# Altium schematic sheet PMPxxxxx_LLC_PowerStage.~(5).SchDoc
size 431 x 279 mm; Date: Not shown in title block; ApprovedBy: Not shown in title block; CheckedBy: Not shown in title block; Author: Not shown in title block; CompanyName: Not shown in title block; Engineer: Not shown in title block; Organization: Not shown in title block; Address1: Not shown in title block; Address2: Not shown in title block; Address3: Not shown in title block; Address4: Not shown in title block; DocumentNumber: 2; Revision: Use project parameter SCH_Rev; SheetNumber: 2; SheetTotal: 4; PageSetup: Record=PageOptions¦CenterHorizontal=True¦CenterVertical=True¦PrintScale=1.00¦XCorrection=1.00¦YCorrection=1.00¦PrintKind=0¦BorderSize=5000000¦LeftOffset=0¦BottomOffset=0¦Orientation=2¦PaperLength=1000¦PaperWidth=1000¦Scale=100¦PaperSource=15¦PrintQuality=600¦MediaType=1¦DitherType=10¦PaperKind=Letter¦PrintScaleMode=1
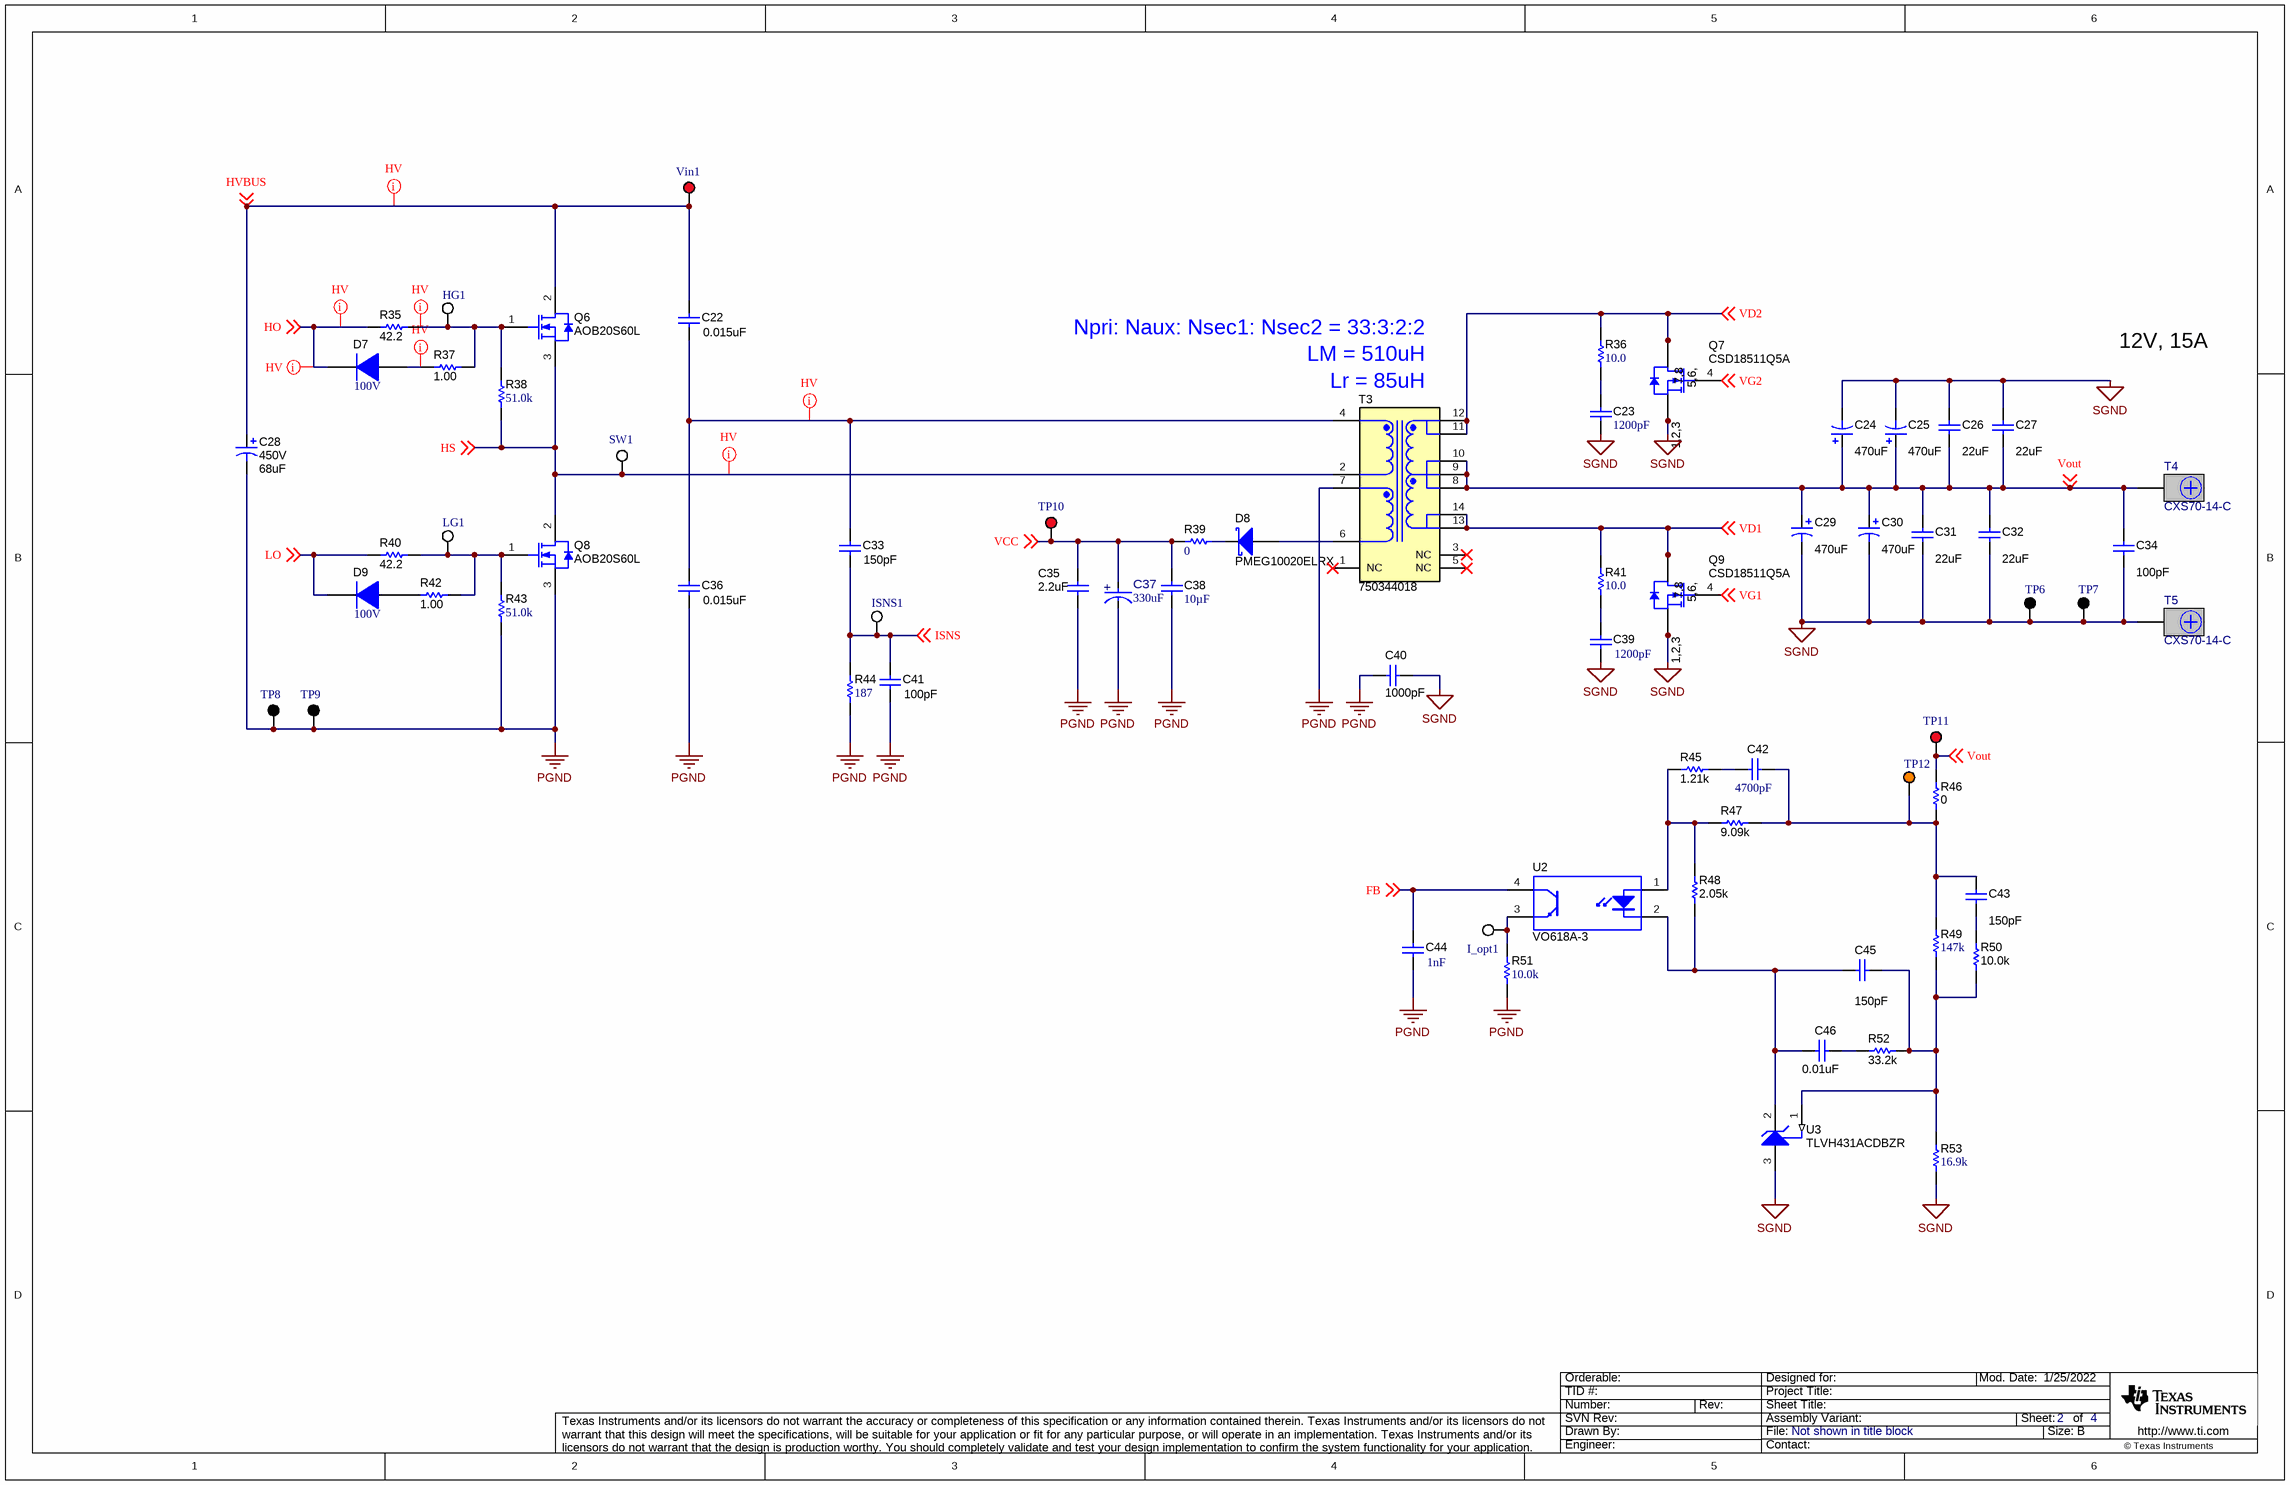
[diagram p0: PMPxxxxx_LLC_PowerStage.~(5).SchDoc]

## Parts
C22  ValueDisplayed: 0.015uF  [B32652_1800x700x1250]  (hidden comment: B32652A7153J000)
C23  ValueDisplayed: 1200pF  [0805L]  (hidden comment: GRM2165C2A122JA01D)
C24  ValueDisplayed: 470uF  [HW_1000x1600]  (hidden comment: UHW1V471MPD)
C25  ValueDisplayed: 470uF  [HW_1000x1600]  (hidden comment: UHW1V471MPD)
C26  ValueDisplayed: 22uF  [1206_190L]  (hidden comment: C3216X5R1E226M160AB)
C27  ValueDisplayed: 22uF  [1206_190L]  (hidden comment: C3216X5R1E226M160AB)
C28  VDC_V: 450V  ValueDisplayed: 68uF  [KXG_1800x3150]  (hidden comment: EKXG451ELL680MMN3S)
C29  ValueDisplayed: 470uF  [HW_1000x1600]  (hidden comment: UHW1V471MPD)
C30  ValueDisplayed: 470uF  [HW_1000x1600]  (hidden comment: UHW1V471MPD)
C31  ValueDisplayed: 22uF  [1206_190L]  (hidden comment: C3216X5R1E226M160AB)
C32  ValueDisplayed: 22uF  [1206_190L]  (hidden comment: C3216X5R1E226M160AB)
C33  ValueDisplayed: 150pF  [1206L]  (hidden comment: GRM31A5C2J151JW01D)
C34  ValueDisplayed: 100pF  [0603L]  (hidden comment: 06035A101FAT2A)
C35  ValueDisplayed: 2.2uF  [0805L]  (hidden comment: C2012X7R1V225K085AC)
C36  ValueDisplayed: 0.015uF  [B32652_1800x700x1250]  (hidden comment: B32652A7153J000)
C37  ValueDisplayed: 330uF  [FP-35ZL330MEFC10X16_RADIAL-MFG]  (hidden comment: 35ZL330MEFC10X16)
C38  ValueDisplayed: 10µF  [1206_180]  (hidden comment: C1206C106J3RACAUTO)
C39  ValueDisplayed: 1200pF  [0805L]  (hidden comment: GRM2165C2A122JA01D)
C40  ValueDisplayed: 1000pF  [CD45_700x600x1100]  (hidden comment: CD45-E2GA102M-NKA)
C41  ValueDisplayed: 100pF  [1206L]  (hidden comment: 12061A101JAT2A)
C42  ValueDisplayed: 4700pF  [0603L]  (hidden comment: C0603C472J1GAC7867)
C43  ValueDisplayed: 150pF  [0402L]  (hidden comment: 885012005062)
C44  Cap_F: 1nF  [1206L]  (hidden comment: 12061A102JAT2A)
C45  ValueDisplayed: 150pF  [0402L]  (hidden comment: 885012005062)
C46  ValueDisplayed: 0.01uF  [0603L]  (hidden comment: 06031C103JAT2A)
D7  Vr_V: 100V  [SOD-123]  (hidden comment: 1N4148W-7-F)
D8  PMEG10020ELRX  [SOD-123W]
D9  Vr_V: 100V  [SOD-123]  (hidden comment: 1N4148W-7-F)
HG1  5012  [Keystone5012]  (value not drawn)
I_opt1  5012  [Keystone5012]  (value not drawn)
ISNS1  5012  [Keystone5012]  (value not drawn)
LG1  5012  [Keystone5012]  (value not drawn)
Q6  AOB20S60L  [DDPAK]
Q7  CSD18511Q5A  [DQJ0008A]
Q8  AOB20S60L  [DDPAK]
Q9  CSD18511Q5A  [DQJ0008A]
R35  ValueDisplayed: 42.2  [0603]  (hidden comment: RC0603FR-0742R2L)
R36  ValueDisplayed: 10.0  [1206L]  (hidden comment: RC1206FR-0710RL)
R37  ValueDisplayed: 1.00  [0603L]  (hidden comment: RC0603FR-071RL)
R38  ValueDisplayed: 51.0k  [0603L]  (hidden comment: RC0603FR-0751KL)
R39  ValueDisplayed: 0  [1206L]  (hidden comment: ERJ-8GEY0R00V)
R40  ValueDisplayed: 42.2  [0603L]  (hidden comment: RC0603FR-0742R2L)
R41  ValueDisplayed: 10.0  [1206L]  (hidden comment: RC1206FR-0710RL)
R42  ValueDisplayed: 1.00  [0603L]  (hidden comment: RC0603FR-071RL)
R43  ValueDisplayed: 51.0k  [0603L]  (hidden comment: RC0603FR-0751KL)
R44  ValueDisplayed: 187  [1206]  (hidden comment: RC1206FR-07187RL)
R45  ValueDisplayed: 1.21k  [0603L]  (hidden comment: RC0603FR-071K21L)
R46  ValueDisplayed: 0  [0402L]  (hidden comment: RC0402JR-070RL)
R47  ValueDisplayed: 9.09k  [0603L]  (hidden comment: RC0603FR-079K09L)
R48  ValueDisplayed: 2.05k  [0603L]  (hidden comment: RC0603FR-072K05L)
R49  ValueDisplayed: 147k  [0603L]  (hidden comment: RC0603FR-07147KL)
R50  ValueDisplayed: 10.0k  [0603L]  (hidden comment: ERJ-3EKF1002V)
R51  ValueDisplayed: 10.0k  [0402L]  (hidden comment: ERJ-2RKF1002X)
R52  ValueDisplayed: 33.2k  [0603L]  (hidden comment: RC0603FR-0733K2L)
R53  ValueDisplayed: 16.9k  [0603L]  (hidden comment: RC0603FR-0716K9L)
SW1  5012  [Keystone5012]  (value not drawn)
T3  750344018  [Wurth_750344018]
T4  CXS70-14-C  [Panduit_CXS70-14-C]
T5  CXS70-14-C  [Panduit_CXS70-14-C]
TP6  5011  [Keystone5011]  (value not drawn)
TP7  5011  [Keystone5011]  (value not drawn)
TP8  5011  [Keystone5011]  (value not drawn)
TP9  5011  [Keystone5011]  (value not drawn)
TP10  5010  [Keystone5010]  (value not drawn)
TP11  5010  [Keystone5010]  (value not drawn)
TP12  5013  [Keystone5013]  (value not drawn)
U2  VO618A-3  [DIP-4]
U3  TLVH431ACDBZR  [DBZ0003A_N]
Vin1  5010  [Keystone5010]  (value not drawn)

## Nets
PGND: C28.2(-) C35.2 C36.2 C37.1(CATHODE) C38.2 C40.2 C41.2 C44.2 Q8.3(S) R43.1 R44.1 R51.1 T3.7 TP8.1 TP9.1
SGND: C23.2 C24.2(-) C25.2(-) C26.1 C27.1 C29.2(-) C30.2(-) C31.2 C32.2 C34.2 C39.2 C40.1 Q7.1(S) Q7.2(S) Q7.3(S) Q9.1(S) Q9.2(S) Q9.3(S) R53.1 T5.1 TP6.1 TP7.1 U3.3(ANODE)
FB: C44.1 U2.4(C) ; off-sheet FB
HO: D7.1(K) R35.1 ; off-sheet HO
HS: Q6.3(S) Q8.2(D) R38.1 SW1.1 T3.2 ; off-sheet HS
HVBUS: C22.1 C28.1(+) Q6.2(D) Vin1.1 ; off-sheet HVBUS
ISNS: C33.2 C41.1 ISNS1.1 R44.2 ; off-sheet ISNS
LO: D9.1(K) R40.1 ; off-sheet LO
VCC: C35.1 C37.2(ANODE) C38.1 R39.1 TP10.1 ; off-sheet VCC
VD1: Q9.5(D) Q9.6(D) Q9.7(D) Q9.8(D) Q9.9(D) R41.2 T3.13 T3.14 ; off-sheet VD1
VD2: Q7.5(D) Q7.6(D) Q7.7(D) Q7.8(D) Q7.9(D) R36.2 T3.11 T3.12 ; off-sheet VD2
VG1: Q9.4(G) ; off-sheet VG1
VG2: Q7.4(G) ; off-sheet VG2
Vout: C24.1(+) C25.1(+) C26.2 C27.2 C29.1(+) C30.1(+) C31.1 C32.1 C34.1 R46.2 T3.8 T3.9 T3.10 T4.1 TP11.1 ; off-sheet Vout
NetC22_2: C22.2 C33.1 C36.1 T3.4
NetC23_1: C23.1 R36.1
NetC39_1: C39.1 R41.1
NetC42_1: C42.1 C43.1 R46.1 R47.2 R49.2 TP12.1
NetC42_2: C42.2 R45.2
NetC43_2: C43.2 R50.2
NetC45_1: C45.1 R49.1 R50.1 R52.1 R53.2 U3.1(REF)
NetC45_2: C45.2 C46.2 R48.1 U2.2(K) U3.2(CATHODE)
NetC46_1: C46.1 R52.2
NetD7_2: D7.2(A) R37.1
NetD8_1: D8.1(K) R39.2
NetD8_2: D8.2(A) T3.6
NetD9_2: D9.2(A) R42.1
NetHG1_1: HG1.1 Q6.1(G) R35.2 R37.2 R38.2
NetI_opt1_1: I_opt1.1 R51.2 U2.3(E)
NetLG1_1: LG1.1 Q8.1(G) R40.2 R42.2 R43.2
NetR45_1: R45.1 R47.1 R48.2 U2.1(A)

Not connected (* = marked no-connect by the designer): T3 1(NC)* 3(NC)* 5(NC)*

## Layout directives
net class HV: HO, HS, HVBUS, NetC22_2, NetD7_2, NetHG1_1

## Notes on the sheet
- LM = 510uH
- Npri: Naux: Nsec1: Nsec2 = 33:3:2:2
- 12V, 15A
- (near T3) Lr = 85uH

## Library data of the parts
C22 C36 = CMP-0012346-3: CAP, Film, 0.015 uF, 1250 V, +/- 5%, AEC-Q200 Grade 3, TH; Manufacturer: TDK; TaMin_C: -55°C; Polarized: N; SizeAreaWB_mm2: 180; Value1: Unknown; TaMax_C: 100°C; SizeZ_mm: 12.5; SizeX_mm: 18; SizeY_mm: 7; Cap_Case: 18x7x12.5; Value2: 1250V; SizeArea_mm2: 126; CompType: Capacitor; AEC Qualified: Y; Cap_F: 15nF; VDC_V: 1.25kV; AEC Grade: 3; AEC Category: Q200
C23 C39 = CMP-0008098-2: CAP, CERM, 1200 pF, 100 V, +/- 5%, C0G/NP0, 0805; Manufacturer: MuRata; TaMin_C: -55°C; Polarized: N; SizeAreaWB_mm2: 6.75; Value1: Unknown; U/M: EA; Value: 1200pF; TaMax_C: 125°C; SizeZ_mm: 1.45; SizeX_mm: 2; SizeY_mm: 1.25; Cap_Case: 0805; Value2: 100V; SizeArea_mm2: 2.5; Cap_F: 1.2nF; AEC Category: Q200
C24 C25 C29 C30 = CMP-0010541-2: CAP, AL, 470 uF, 35 V, +/- 20%, 0.03 ohm, TH; Manufacturer: Nichicon; TaMin_C: -40°C; ESR_ohm: 0.03; Polarized: Y; SizeAreaWB_mm2: 144; U/M: EA; Value: 470uF; TaMax_C: 105°C; SizeZ_mm: 17.5; SizeX_mm: 10; Cap_Case: 10x16mm; Value2: 35V; SizeArea_mm2: 100; CompType: Capacitor; AEC Qualified: N; Cap_F: 470µF; IRMS_A: 2A; AEC Category: Q200
C26 C27 C31 C32 = CMP-0008654-2: CAP, CERM, 22 uF, 25 V, +/- 20%, X5R, 1206_190; Manufacturer: TDK; TaMin_C: -55°C; Polarized: N; SizeAreaWB_mm2: 10.92; Value1: Unknown; U/M: EA; Value: 22uF; TaMax_C: 85°C; SizeZ_mm: 1.9; SizeX_mm: 3.2; SizeY_mm: 1.6; Cap_Case: 1206; Value2: 25V; SizeArea_mm2: 5.12; CompType: Capacitor; Cap_F: 22µF; AEC Category: Q200
C28 = CMP-0010043-2: CAP, AL, 68 uF, 450 V, +/- 20%, TH; Manufacturer: Chemi-Con; TaMin_C: -25°C; Polarized: Y; SizeAreaWB_mm2: 400; Value1: Unknown; U/M: EA; Value: 68uF; TaMax_C: 105°C; SizeZ_mm: 33; SizeX_mm: 18; Cap_Case: 18x31.5mm; SizeArea_mm2: 324; CompType: Capacitor; Cap_F: 68µF; IRMS_A: 6.3dA; AEC Category: Q200
C33 = CMP-0008885-2: CAP, CERM, 150 pF, 630 V, +/- 5%, C0G/NP0, 1206; Manufacturer: MuRata; TaMin_C: -55°C; Polarized: N; SizeAreaWB_mm2: 10.92; Value1: Unknown; U/M: EA; Value: 150pF; TaMax_C: 125°C; SizeZ_mm: 1.35; SizeX_mm: 3.2; SizeY_mm: 1.6; Cap_Case: 1206; Value2: 630V; SizeArea_mm2: 5.12; CompType: Capacitor; AEC Category: Q200
C34 = CMP-0006762-4: CAP, CERM, 100 pF, 50 V, +/- 1%, C0G/NP0, 0603; Manufacturer: AVX; TaMin_C: -55°C; Polarized: N; SizeAreaWB_mm2: 4.68; Value1: Unknown; U/M: EA; TaMax_C: 125°C; SizeZ_mm: 1; SizeX_mm: 1.6; SizeY_mm: 0.8; Cap_Case: 0603; Value2: 50V; SizeArea_mm2: 1.28; CompType: Capacitor; Value: 100pF; AEC Category: Q200
C35 = CMP-0007883-2: CAP, CERM, 2.2 uF, 35 V, +/- 10%, X7R, 0805; Manufacturer: TDK; TaMin_C: -55°C; Polarized: N; SizeAreaWB_mm2: 6.75; Value1: Unknown; U/M: EA; Value: 2.2uF; TaMax_C: 125°C; SizeZ_mm: 1.45; SizeX_mm: 2; SizeY_mm: 1.25; Cap_Case: 0805; Value2: 35V; SizeArea_mm2: 2.5; CompType: Capacitor; Cap_F: 2.2µF; AEC Category: Q200
C37 = CMP-0098283-1: Cap Aluminum Lytic 330uF 35V 20% (10 X 16mm) Radial 5mm 1430mA 4000h 105C Bulk; Manufacturer: Rubycon; AEC Qualified: No; Cap_F: 330µF; IRMS_A: 1.43A; SizeZ_mm: 17.5mm; Dissipation Factor: 12%; Leakage Current: 115.5uA; Life: 4000Hours; Value: 330µF
C38 = CMP-0081062-1: CAP, CERM, 10 µF, 25 V,+/- 5%, X7R, AEC-Q200 Grade 1, 1206; Manufacturer: Kemet; TaMin_C: -55°C; Polarized: N; SizeAreaWB_mm2: 10.92; U/M: EA; Value: 10uF; TaMax_C: 125°C; SizeZ_mm: 1.8; SizeX_mm: 3.2; SizeY_mm: 1.6; Value2: 25V; SizeArea_mm2: 5.12; AEC Qualified: Y; AEC Grade: 1; AEC Category: Q200
C40 = CMP-0009595-2: CAP, CERM, 1000 pF,  V, +/- 20%, E, D7xT6mm; Manufacturer: TDK; TaMin_C: -25°C; Polarized: N; SizeAreaWB_mm2: 101.2; Value1: Unknown; U/M: EA; Value: 1000pF; TaMax_C: 125°C; SizeZ_mm: 11; SizeX_mm: 10.65; SizeY_mm: 6; Cap_Case: 7x6x11mm; SizeArea_mm2: 63.9; Cap_F: 1nF; AEC Category: Q200
C41 = CMP-0008462-2: CAP, CERM, 100 pF, 100 V, +/- 5%, C0G/NP0, 1206; Manufacturer: AVX; TaMin_C: -55°C; ESR_ohm: 7.01d; Polarized: N; SizeAreaWB_mm2: 10.92; Value1: 0.701 ohm; U/M: EA; Value: 100pF; TaMax_C: 125°C; SizeZ_mm: 1.35; SizeX_mm: 3.2; SizeY_mm: 1.6; Cap_Case: 1206; Value2: 100V; SizeArea_mm2: 5.12; CompType: Capacitor; AEC Category: Q200
C42 = CMP-0006941-4: CAP, CERM, 4700 pF, 100 V, +/- 5%, C0G/NP0, 0603; Manufacturer: Kemet; TaMin_C: -55°C; Polarized: N; SizeAreaWB_mm2: 4.68; Value1: Unknown; U/M: EA; Value: 4700pF; TaMax_C: 125°C; SizeZ_mm: 1; SizeX_mm: 1.6; SizeY_mm: 0.8; Cap_Case: 0603; Value2: 100V; SizeArea_mm2: 1.28; Cap_F: 4.7nF; AEC Category: Q200
C43 C45 = CMP-0064913-2: CAP, CERM, 150 pF, 50 V,+/- 5%, C0G/NP0, 0402; Manufacturer: Wurth Elektronik; TaMin_C: -55°C; Polarized: N; SizeAreaWB_mm2: 3; Value1: Unknown; U/M: EA; Value: 150pF; TaMax_C: 125°C; SizeZ_mm: 0.6; SizeX_mm: 1; SizeY_mm: 0.5; Cap_Case: 0402; Value2: 50V; CompType: Capacitor; AEC Category: Q200
C44 = CMP-0008465-2: CAP, CERM, 1000 pF, 100 V, +/- 5%, C0G/NP0, 1206; Manufacturer: AVX; TaMin_C: -55°C; ESR_ohm: 2.38d; Polarized: N; SizeAreaWB_mm2: 10.92; Value1: 0.238 ohm; U/M: EA; Value: 1000pF; TaMax_C: 125°C; SizeZ_mm: 1.35; SizeX_mm: 3.2; SizeY_mm: 1.6; Cap_Case: 1206; Value2: 100V; SizeArea_mm2: 5.12; AEC Category: Q200
C46 = CMP-0006726-4: CAP, CERM, 0.01 uF, 100 V, +/- 5%, X7R, 0603; Manufacturer: AVX; TaMin_C: -55°C; ESR_ohm: 0.098; Polarized: N; SizeAreaWB_mm2: 4.68; Value1: 0.098 ohm; U/M: EA; Value: 0.01uF; TaMax_C: 125°C; SizeZ_mm: 1; SizeX_mm: 1.6; SizeY_mm: 0.8; Cap_Case: 0603; Value2: 100V; SizeArea_mm2: 1.28; Cap_F: 10nF; AEC Category: Q200
D7 D9 = CMP-0029001-2: Diode, Ultrafast, 100 V, 0.15 A, SOD-123; Manufacturer: Diodes Inc.; Io_A: 150mA; Green_Lifecycle: Active; SizeAreaWB_mm2: 13.095; Green_REACh: Passed; Value1: 0.15A; TJmax_C: 150°C; Value: 100V; SizeZ_mm: 1.35; SizeX_mm: 3.85; SizeY_mm: 1.7; Vf_V: 1.25V; SizeArea_mm2: 6.545; AEC Category: Q101
D8 = CMP-0028977-2: Diode, Schottky, 100 V, 2 A, AEC-Q101, SOD-123W; Manufacturer: Nexperia; Io_A: 2A; SizeAreaWB_mm2: 12.15; Vr_V: 100V; TJmax_C: 175°C; Value: 100V; SizeZ_mm: 1; SizeX_mm: 3.5; SizeY_mm: 1.7; Vf_V: 830mV; Value2: 0.83V; SizeArea_mm2: 5.95; AEC Qualified: Y; AEC Category: Q101
HG1 I_opt1 ISNS1 LG1 SW1 = CMP-0055149-2: Test Point, Multipurpose, White, TH; Manufacturer: Keystone Electronics; CNHeader: FALSE; Green_Lifecycle: Active; Green_REACh: Passed; ContactFinish: Silver; CT: TRUE
Q6 Q8 = CMP-0001135-4: MOSFET, N-CH, 600 V, 20 A, DDPAK; Alternate Manufacturer: None; Manufacturer: AOS; SizeZ_mm: 4.445; ChType: N; Value2: 19.8 nC; VdsMax_V: 600V; SizeX_mm: 15.245; SizeAreaWB_mm2: 209.6992; SizeY_mm: 10.16; Vgs_V: 30V; QgTyp_nC: 19.8; Value: 600V; SizeArea_mm2: 154.8892; AEC Category: Q101; IdsMax_A: 20A; ChMode: Enhancement
Q7 Q9 = CMP-0000711-1: MOSFET, N-CH, 40 V, 100 A, DQJ0008A (VSONP-8); Alternate Manufacturer: None; Manufacturer: Texas Instruments; SizeZ_mm: 1.1; ChType: N; Value2: 63 nC; Value1: 0.003; VdsMax_V: 40V; SizeX_mm: 6; SizeY_mm: 4.9; Vgs_V: 20V; Value: 40V; Rdson45_ohm: 3.5m; SizeArea_mm2: 29.4; AEC Category: Q101; IdsMax_A: 100A; SizeAreaWB_mm2: 55.2; U/M: EA; QgTyp_nC: 63
R35 R40 = CMP-0023107-5: RES, 42.2, 1%, 0.1 W, 0603; Manufacturer: Yageo; Power_W: 100mW; TempCo: 100 ppm/C; Value_Code: 42R2; Value: 42.2; EIA_Code: E96; SizeX_mm: 1.6; SizeY_mm: 0.8; SizeZ_mm: 1; Value2: 0.1W; SizeArea_mm2: 1.28; CompType: Resistor; AEC Qualified: N; VDC_V: 75V; AEC Category: Q200; SizeAreaWB_mm2: 4.68
R36 R41 = CMP-0017851-2: RES, 10.0, 1%, 0.25 W, 1206; Manufacturer: Yageo America; Power_W: 250mW; TempCo: 200 ppm/C; Value_Code: 10R0; U/M: EA; Value: 10.0; EIA_Code: E96; Res_ohm: 10; SizeX_mm: 3.2; SizeY_mm: 1.6; SizeZ_mm: 1.35; Value2: 0.25W; SizeArea_mm2: 5.12; VDC_V: 200V; AEC Category: Q200
R37 R42 = CMP-0022900-4: RES, 1.00, 1%, 0.1 W, 0603; Manufacturer: Yageo; Power_W: 100mW; TempCo: 200 ppm/C; Value_Code: 1R00; Value: 1.00; EIA_Code: E96; Res_ohm: 1; SizeX_mm: 1.6; SizeY_mm: 0.8; Value2: 0.1W; SizeArea_mm2: 1.28; CompType: Resistor; AEC Qualified: N; VDC_V: 75V; AEC Category: Q200; SizeAreaWB_mm2: 4.68
R38 R43 = CMP-0023167-5: RES, 51.0 k, 1%, 0.1 W, 0603; Manufacturer: Yageo; Power_W: 100mW; TempCo: 100 ppm/C; Value_Code: 51k0; Value: 51.0k; Res_ohm: 51k; SizeX_mm: 1.6; SizeY_mm: 0.8; SizeZ_mm: 1; Value2: 0.1W; SizeArea_mm2: 1.28; AEC Qualified: N; VDC_V: 75V; AEC Category: Q200; SizeAreaWB_mm2: 4.68
R39 = CMP-0018748-3: RES, 0, 5%, 0.25 W, AEC-Q200 Grade 0, 1206; Manufacturer: Panasonic; Power_W: 250mW; TempCo: 600 ppm/C; Value_Code: 0000; Value: 0; EIA_Code: E24; SizeX_mm: 3.2; SizeY_mm: 1.6; SizeZ_mm: 1.35; Value2: 0.25W; SizeArea_mm2: 5.12; AEC Qualified: Y; VDC_V: 200V; AEC Category: Q200; SizeAreaWB_mm2: 10.92
R44 = CMP-0017949-2: RES, 187, 1%, 0.25 W, 1206; Manufacturer: Yageo America; Power_W: 250mW; TempCo: 100 ppm/C; Value_Code: 187R; U/M: EA; Value: 187; EIA_Code: E96; SizeX_mm: 3.2; SizeY_mm: 1.6; SizeZ_mm: 1.35; Value2: 0.25W; SizeArea_mm2: 5.12; VDC_V: 200V; AEC Category: Q200
R45 = CMP-0022871-5: RES, 1.21 k, 1%, 0.1 W, 0603; Manufacturer: Yageo; Power_W: 100mW; TempCo: 100 ppm/C; Value_Code: 1k21; Value: 1.21k; EIA_Code: E96; SizeX_mm: 1.6; SizeY_mm: 0.8; SizeZ_mm: 1; Value2: 0.1W; SizeArea_mm2: 1.28; AEC Qualified: N; VDC_V: 75V; AEC Category: Q200; SizeAreaWB_mm2: 4.68
R46 = CMP-0027004-2: RES, 0, 5%, 0.063 W, 0402; Manufacturer: Yageo America; Power_W: 63mW; TempCo: 200 ppm/C; Value_Code: 0000; U/M: EA; Value: 0; EIA_Code: E24; SizeX_mm: 1; SizeY_mm: 0.5; SizeZ_mm: 0.6; Value2: 0.063W; CompType: Resistor; VDC_V: 50V; AEC Category: Q200
R47 = CMP-0023332-5: RES, 9.09 k, 1%, 0.1 W, 0603; Manufacturer: Yageo; Power_W: 100mW; TempCo: 100 ppm/C; Value_Code: 9k09; Value: 9.09k; EIA_Code: E96; SizeX_mm: 1.6; SizeY_mm: 0.8; SizeZ_mm: 1; Value2: 0.1W; SizeArea_mm2: 1.28; AEC Qualified: N; VDC_V: 75V; AEC Category: Q200; SizeAreaWB_mm2: 4.68
R48 = CMP-0022981-5: RES, 2.05 k, 1%, 0.1 W, 0603; Manufacturer: Yageo; Power_W: 100mW; TempCo: 100 ppm/C; Value_Code: 2k05; Value: 2.05k; EIA_Code: E96; SizeX_mm: 1.6; SizeY_mm: 0.8; SizeZ_mm: 1; Value2: 0.1W; SizeArea_mm2: 1.28; AEC Qualified: N; VDC_V: 75V; AEC Category: Q200; SizeAreaWB_mm2: 4.68
R49 = CMP-0022800-4: RES, 147 k, 1%, 0.1 W, 0603; Manufacturer: Yageo; Power_W: 100mW; TempCo: 100 ppm/C; Value: 147k; EIA_Code: E96; SizeX_mm: 1.6; SizeY_mm: 0.8; SizeZ_mm: 1; Value2: 0.1W; SizeArea_mm2: 1.28; AEC Qualified: N; VDC_V: 75V; AEC Category: Q200; SizeAreaWB_mm2: 4.68
R50 = CMP-0022684-3: RES, 10.0 k, 1%, 0.1 W, 0603; Manufacturer: Panasonic; Power_W: 100mW; TempCo: 100 ppm/C; Value_Code: 10k0; U/M: EA; Value: 10.0k; EIA_Code: E96; Res_ohm: 10k; SizeX_mm: 1.6; SizeY_mm: 0.8; SizeZ_mm: 1; Value2: 0.1W; SizeArea_mm2: 1.28; CompType: Resistor; VDC_V: 75V; AEC Category: Q200
R51 = CMP-0026658-1: RES, 10.0 k, 1%, 0.1 W, 0402; Manufacturer: Panasonic; Power_W: 100mW; TempCo: 100 ppm/C; Value_Code: 10k0; U/M: EA; Value: 10.0k; EIA_Code: E96; Res_ohm: 10k; SizeX_mm: 1; SizeY_mm: 0.5; SizeZ_mm: 0.6; Value2: 0.1W; VDC_V: 50V; AEC Category: Q200
R52 = CMP-0023036-5: RES, 33.2 k, 1%, 0.1 W, 0603; Manufacturer: Yageo; Power_W: 100mW; TempCo: 100 ppm/C; Value_Code: 33k2; Value: 33.2k; EIA_Code: E96; SizeX_mm: 1.6; SizeY_mm: 0.8; SizeZ_mm: 1; Value2: 0.1W; SizeArea_mm2: 1.28; AEC Qualified: N; VDC_V: 75V; AEC Category: Q200; SizeAreaWB_mm2: 4.68
R53 = CMP-0022830-5: RES, 16.9 k, 1%, 0.1 W, 0603; Manufacturer: Yageo; Power_W: 100mW; TempCo: 100 ppm/C; Value_Code: 16k9; Value: 16.9k; EIA_Code: E96; SizeX_mm: 1.6; SizeY_mm: 0.8; SizeZ_mm: 1; Value2: 0.1W; SizeArea_mm2: 1.28; AEC Qualified: N; VDC_V: 75V; AEC Category: Q200; SizeAreaWB_mm2: 4.68
T3 = CMP-0081993-1: Transformer, 510 uH, TH; Manufacturer: Wurth Elektronik; SizeAreaWB_mm2: 1732.5; SizeArea_mm2: 1569.5; AEC Qualified: N; Ns2toNp: 0.06; Lp: 510; AEC Category: Q200; Value: 510uH; SizeZ_mm: 26.5; Ind_H: 510µH; SizeY_mm: 43; LeakageInd_H: 85µH; SizeX_mm: 36.5
T4 T5 = CMP-0075010-2: Terminal 70A Lug; Manufacturer: Panduit; CNHeader: False; Green_Lifecycle: Not Set; Green_REACh: Incomplete; CompType: Screw Terminal
TP6 TP7 = CMP-0055148-2: Test Point, Multipurpose, Black, TH; Manufacturer: Keystone Electronics; CNHeader: FALSE; ContactFinish: Silver; Green_REACh: Passed; Green_Lifecycle: Active; CT: TRUE
TP8 TP9 = CMP-0055148-2: Test Point, Multipurpose, Black, TH; Manufacturer: Keystone Electronics; CNHeader: FALSE; Green_Lifecycle: Active; Green_REACh: Passed; ContactFinish: Silver; CT: TRUE
TP10 TP11 Vin1 = CMP-0055147-2: Test Point, Multipurpose, Red, TH; Manufacturer: Keystone Electronics; CNHeader: FALSE; Green_Lifecycle: Active; Green_REACh: Passed; ContactFinish: Silver; CT: TRUE
TP12 = CMP-0055150-2: Test Point, Multipurpose, Orange, TH; Manufacturer: Keystone Electronics; CNHeader: FALSE; Green_Lifecycle: Active; Green_REACh: Passed; ContactFinish: Silver; CT: TRUE
U2 = CMP-0083653-1: Optocoupler, 5.3 kV, 100-200% CTR, SMT; Manufacturer: Vishay-Semiconductor; CTR (Max): 200%; SizeAreaWB_mm2: 71.064; CTR (Min): 100%; SizeZ_mm: 5; SizeX_mm: 8.8; SizeY_mm: 4.58; SizeArea_mm2: 40.304; Voltage_Isolation_Vrms: 5.3kV
U3 = CMP-0033066-1: Low-Voltage Adjustable Precision Shunt Regulator, 129 ppm / degC, 80 mA, 0 to 70 degC, 3-pin SOT-23 (DBZ), Green (RoHS & no Sb/Br); Manufacturer: Texas Instruments; Min Iz for Regulation(uA): 80; VO Adj(Max)(V): 18; VO Adj(Min)(V): 1.24; Rating: Catalog; SubFamily: Shunt Voltage Reference; Temp Coeff(Max)(ppm/ degree C): 129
